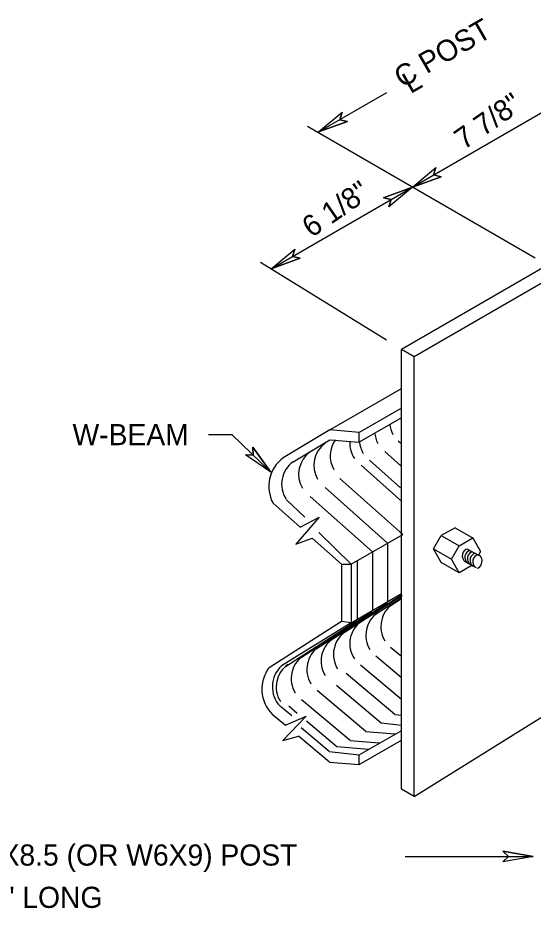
# Model space of a CAD drawing. Extents: x 12.4 to 19.6, y 6 to 16.
# Drawn here: x 15.965 to 17.428, y 13.444 to 15.97 of the extents above; entities that cross this region are included whole.
import ezdxf

# ---------------------------------------------------------------- set-up
doc = ezdxf.new("R2010")
doc.units = 0
for name, color, linetype in [('DETL-DIMS', 7, 'Continuous'), ('DETL-LINE', 7, 'Continuous'), ('DETL-NOTE', 7, 'Continuous'), ('DETL-PATT', 7, 'Continuous')]:
    doc.layers.add(name, color=color, linetype=linetype)

msp = doc.modelspace()

# ---------------------------------------------------------------- linework, layer by layer
at = {"layer": 'DETL-DIMS'}
for p, q in [((16.8192, 15.6465), (17.0128, 15.7583)), ((17.0855, 15.4896), (17.549, 15.7572)), ((16.8192, 15.6465), (16.8859, 15.7025)), ((16.8795, 15.6813), (16.8859, 15.7025)), ((17.434, 15.2882), (16.7876, 15.6617)), ((16.8192, 15.6465), (16.9011, 15.6763)), ((16.9011, 15.6763), (16.8795, 15.6813)), ((17.0855, 15.4896), (17.1522, 15.5456)), ((17.1458, 15.5244), (17.1522, 15.5456)), ((17.0855, 15.4896), (17.1674, 15.5194)), ((17.1674, 15.5194), (17.1458, 15.5244)), ((16.6848, 15.2583), (17.0855, 15.4896)), ((17.0855, 15.4896), (17.0036, 15.4598)), ((17.0855, 15.4896), (17.0188, 15.4336)), ((17.0036, 15.4598), (17.0252, 15.4548)), ((17.0252, 15.4548), (17.0188, 15.4336)), ((16.6848, 15.2583), (16.7515, 15.3143)), ((16.7451, 15.2931), (16.7515, 15.3143)), ((16.6848, 15.2583), (16.7667, 15.2881)), ((16.7667, 15.2881), (16.7451, 15.2931)), ((17.0122, 15.0558), (16.6545, 15.2759)), ((16.5066, 14.7878), (16.5731, 14.7878)), ((16.5731, 14.7878), (16.6839, 14.6815)), ((16.6839, 14.6815), (16.6115, 14.73)), ((16.6337, 14.7297), (16.6115, 14.73)), ((16.6839, 14.6815), (16.6325, 14.7518)), ((16.6325, 14.7518), (16.6337, 14.7297)), ((17.0651, 13.5912), (17.4282, 13.5912)), ((17.4282, 13.5912), (17.3424, 13.6063)), ((17.3424, 13.6063), (17.3586, 13.5912)), ((17.4282, 13.5912), (17.3424, 13.5761)), ((17.3586, 13.5912), (17.3424, 13.5761))]:
    msp.add_line(p, q, dxfattribs=at)
for points in [[(16.9011, 15.6763), (16.8192, 15.6465), (16.8859, 15.7025), (16.8795, 15.6813)], [(17.1674, 15.5194), (17.0855, 15.4896), (17.1522, 15.5456), (17.1458, 15.5244)], [(17.0036, 15.4598), (17.0855, 15.4896), (17.0188, 15.4336), (17.0252, 15.4548)], [(16.7667, 15.2881), (16.6848, 15.2583), (16.7515, 15.3143), (16.7451, 15.2931)], [(16.6325, 14.7518), (16.6839, 14.6815), (16.6115, 14.73), (16.6337, 14.7297)], [(17.3424, 13.6063), (17.4282, 13.5912), (17.3424, 13.5761), (17.3586, 13.5912)]]:
    msp.add_lwpolyline(points, close=True, dxfattribs=at)
at = {"layer": 'DETL-LINE'}
for p, q in [((17.9191, 15.5286), (17.0548, 15.0296)), ((17.9551, 15.5078), (17.0908, 15.0088)), ((17.0548, 13.7822), (17.0548, 15.0296)), ((17.0908, 15.0088), (17.0548, 15.0296)), ((17.0908, 13.7614), (17.0908, 15.0088)), ((16.8508, 14.8009), (17.0548, 14.9188)), ((17.0548, 14.8633), (16.9348, 14.794)), ((17.0548, 14.8356), (16.9348, 14.7663)), ((16.8508, 14.8009), (16.7188, 14.7218)), ((16.9348, 14.794), (16.8508, 14.8009)), ((16.9348, 14.7663), (16.9348, 14.794)), ((16.7469, 14.7109), (16.8508, 14.7732)), ((16.8508, 14.7732), (16.9348, 14.7663)), ((17.0513, 14.7636), (17.0447, 14.7694)), ((16.7282, 14.6031), (16.7806, 14.5532)), ((16.69, 14.5929), (16.7666, 14.5249)), ((16.8211, 14.5536), (16.7548, 14.4771)), ((16.7666, 14.5249), (16.8211, 14.5536)), ((16.82, 14.5098), (16.9117, 14.4203)), ((16.9117, 14.4203), (17.0582, 14.5048)), ((17.1454, 14.4636), (17.1676, 14.502)), ((17.2071, 14.523), (17.1676, 14.502)), ((17.1676, 14.502), (17.2184, 14.4727)), ((17.2071, 14.523), (17.2578, 14.4937)), ((16.7548, 14.4771), (16.8012, 14.494)), ((16.884, 14.4203), (16.8012, 14.494)), ((17.2184, 14.4727), (17.2568, 14.4949)), ((17.2568, 14.4949), (17.279, 14.4565)), ((17.1676, 14.4252), (17.1454, 14.4636)), ((17.1454, 14.4636), (17.1962, 14.4343)), ((17.1962, 14.4343), (17.2184, 14.4727)), ((17.2419, 14.4628), (17.2727, 14.4457)), ((17.279, 14.4565), (17.2728, 14.4456)), ((17.2184, 14.3959), (17.1676, 14.4252)), ((17.2184, 14.3959), (17.1962, 14.4343)), ((17.267, 14.4096), (17.2352, 14.4272)), ((16.884, 14.4203), (16.9117, 14.4203)), ((16.884, 14.4203), (16.884, 14.2576)), ((16.9117, 14.4203), (16.9117, 14.2541)), ((17.2544, 14.4166), (17.2184, 14.3959)), ((16.9117, 14.2541), (17.0548, 14.3366)), ((16.6792, 14.1273), (16.884, 14.2585)), ((16.9117, 14.2541), (16.7141, 14.1319)), ((16.9117, 14.2541), (16.884, 14.2576)), ((16.6872, 13.9951), (16.725, 13.9635)), ((16.711, 14.0177), (16.7431, 13.9905)), ((16.7837, 13.9891), (16.7175, 13.9201)), ((16.725, 13.9635), (16.7837, 13.9891)), ((17.0908, 13.7614), (17.4646, 13.9937)), ((16.8492, 13.8887), (16.7696, 13.9561)), ((16.9348, 13.8792), (17.0538, 13.9479)), ((16.7175, 13.9201), (16.7626, 13.932)), ((16.8504, 13.8585), (16.7626, 13.932)), ((16.9348, 13.8515), (17.0548, 13.9208)), ((16.8492, 13.8887), (16.9348, 13.8792)), ((16.9348, 13.8515), (16.9348, 13.8792)), ((16.8504, 13.8585), (16.9348, 13.8515)), ((17.0908, 13.7614), (17.0548, 13.7822))]:
    msp.add_line(p, q, dxfattribs=at)
for centre, radius, start, end in [((16.7785, 14.6408), 0.1006, 126.3688, 208.4427), ((16.7925, 14.6475), 0.0781, 125.7321, 213.287), ((16.7588, 14.0658), 0.1006, 142.5573, 224.6312), ((16.7683, 14.0726), 0.0804, 132.4126, 223.5281)]:
    msp.add_arc(centre, radius, start, end, dxfattribs=at)
for centre, major_axis, ratio, start_param, end_param in [((17.2428, 14.4438), (0.0008, -0.019), 0.830518, 3.141613, 5.735204), ((17.2428, 14.4438), (0.0008, -0.019), 0.830518, 3.141613, 5.735204), ((17.2502, 14.4397), (0.0008, -0.019), 0.830518, 3.141613, 5.735204), ((17.2502, 14.4397), (0.0008, -0.019), 0.830518, 3.141613, 5.735204), ((17.2576, 14.4355), (0.0008, -0.019), 0.830518, 3.141613, 5.735204), ((17.2576, 14.4355), (0.0008, -0.019), 0.830518, 3.141613, 5.735204), ((17.2651, 14.4314), (0.0008, -0.019), 0.830518, 3.141613, 5.735204), ((17.2651, 14.4314), (0.0008, -0.019), 0.830518, 3.141613, 5.735204), ((17.2725, 14.4273), (0.0008, -0.019), 0.830518, 3.141613, 5.735204), ((17.2701, 14.4277), (-0.0028, -0.0186), 0.686958, 0.185971, 3.532023)]:
    msp.add_ellipse(centre, major_axis=major_axis, ratio=ratio, start_param=start_param, end_param=end_param, dxfattribs=at)
at = {"layer": 'DETL-PATT'}
for p, q in [((17.0528, 14.6991), (17.007, 14.7398)), ((17.0516, 14.6371), (16.964, 14.7149)), ((17.0558, 14.5977), (16.9398, 14.7007)), ((17.0582, 14.5048), (16.8799, 14.6633)), ((17.0151, 14.48), (16.8376, 14.6378)), ((16.972, 14.4551), (16.7952, 14.6122)), ((17.0151, 14.4799), (17.0151, 14.3137)), ((16.972, 14.4551), (16.972, 14.2889)), ((16.929, 14.4302), (16.929, 14.2641)), ((16.8524, 14.2039), (17.0553, 14.3337)), ((16.8948, 14.2283), (17.0556, 14.3312)), ((16.934, 14.2537), (17.0564, 14.3321)), ((16.9796, 14.2774), (17.0549, 14.3255)), ((17.0221, 14.3019), (17.0545, 14.3226)), ((16.8122, 14.1805), (17.0151, 14.3104)), ((16.7675, 14.1549), (16.9704, 14.2847)), ((16.7251, 14.1304), (16.928, 14.2602)), ((17.0541, 14.1587), (17.0238, 14.184)), ((17.054, 14.0987), (16.9817, 14.1592)), ((17.0543, 14.0367), (16.9383, 14.1338)), ((17.0361, 13.9937), (16.8974, 14.1097)), ((16.87, 14.0771), (16.9966, 13.9705)), ((16.9535, 13.9458), (16.8154, 14.0615)), ((16.9088, 13.9202), (16.7711, 14.0355)), ((16.7343, 14.0182), (16.7586, 13.9976)), ((16.8708, 13.9022), (16.785, 13.9751)), ((16.9966, 13.9705), (17.0548, 13.9633)), ((17.0541, 13.9911), (17.0352, 13.9927)), ((17.0366, 13.9379), (16.9526, 13.9448)), ((16.9919, 13.9122), (16.9079, 13.9192)), ((16.9616, 13.8947), (16.8708, 13.9022))]:
    msp.add_line(p, q, dxfattribs=at)
for centre, start, end in [((17.0992, 14.8246), 185.593, 207.9678), ((17.0561, 14.7998), 185.1018, 208.3682), ((16.8838, 14.7003), 125.7321, 209.9494), ((16.9303, 14.7274), 144.3194, 209.5724), ((16.9858, 14.7635), 176.7663, 213.919), ((17.013, 14.7749), 184.9937, 211.0946), ((17.0992, 14.8246), 225.7438, 225.974), ((16.8407, 14.6754), 125.7321, 210.3636), ((17.074, 14.2431), 125.0189, 211.4352), ((17.0316, 14.2186), 125.0154, 211.4998), ((16.986, 14.195), 125.0154, 213.2851), ((16.9396, 14.1644), 125.0154, 211.6207), ((16.9043, 14.1451), 125.0154, 211.6811), ((16.8641, 14.1218), 125.0154, 211.6581), ((16.8195, 14.0961), 125.0154, 211.8163), ((16.777, 14.0716), 125.0154, 211.8767)]:
    msp.add_arc(centre, 0.0781, start, end, dxfattribs=at)

# ---------------------------------------------------------------- texts
at = {"layer": 'DETL-NOTE'}
for s, rotation, p in [('C POST ', 29.9984, (17.0562, 15.7699)), ('L', 29.9704, (17.0799, 15.7534)), ('7 7/8"', 34.7406, (17.2316, 15.5943)), ('6 1/8"', 34.7406, (16.7994, 15.3449))]:
    msp.add_text(s, height=0.06, rotation=rotation, dxfattribs=at).set_placement(p)
for s, p in [('W-BEAM', (16.1208, 14.7578)), ('W6X8.5 (OR W6X9) POST', (15.7962, 13.5651)), ('6\'-0" LONG', (15.7962, 13.4451))]:
    msp.add_text(s, height=0.06, dxfattribs=at).set_placement(p)

doc.saveas('drawing.dxf')
